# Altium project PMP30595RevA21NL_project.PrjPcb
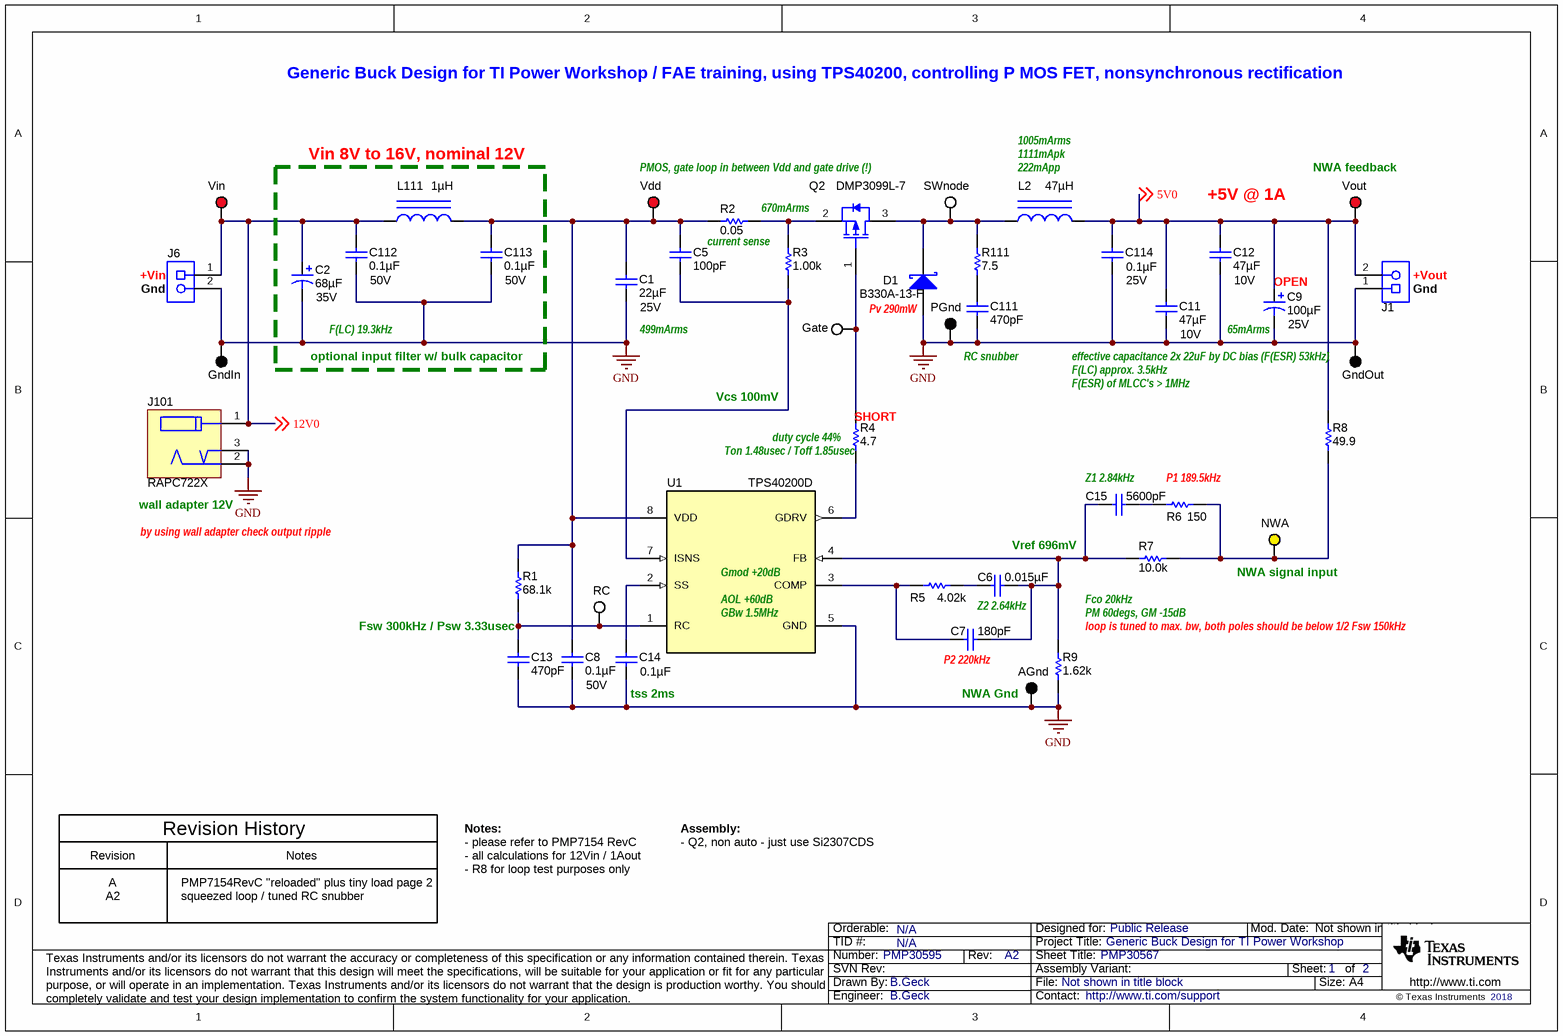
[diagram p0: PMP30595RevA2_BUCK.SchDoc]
CopyrightYear: 2018; EVM_Orderable: N/A; PCB_Rev: A21NL; PRJ_Customer: Public Release; PRJ_Engineer: B.Geck; PRJ_Number: PMP30595; PRJ_Title: Generic Buck Design for TI Power Workshop; SCH_Rev: A2; TechSupport: http://www.ti.com/support; TID: N/A
2 sheets, 77 parts. Net scope: global (net labels, ports and power ports of the same name join across sheets).
Board file: PMP30595RevA21NL_board.PcbDoc
Sheets:
  PMP30595RevA2_BUCK.SchDoc
  PMP30595RevA2_LOAD.SchDoc

## Sheet PMP30595RevA2_BUCK.SchDoc: PMP30567
size A4; Date: Not shown in title block; ApprovedBy: Not shown in title block; CheckedBy: Not shown in title block; Author: Not shown in title block; CompanyName: Not shown in title block; DrawnBy: B.Geck; Organization: Not shown in title block; Address1: Not shown in title block; Address2: Not shown in title block; Address3: Not shown in title block; Address4: Not shown in title block; DocumentNumber: 1; Revision: Use project parameter SCH_Rev; SheetNumber: 1; SheetTotal: 2; PageSetup: Record=PageOptions¦CenterHorizontal=True¦CenterVertical=True¦PrintScale=0.62¦XCorrection=1.00¦YCorrection=1.00¦PrintKind=0¦BorderSize=5000000¦LeftOffset=0¦BottomOffset=0¦Orientation=2¦PaperLength=1000¦PaperWidth=1000¦Scale=100¦PaperSource=15¦PrintQuality=600¦MediaType=1¦DitherType=10¦PrintScaleMode=1¦PaperKind=Letter

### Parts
AGnd  5011  [Keystone5011]  (value not drawn)
C1  ValueDisplayed: 22µF  Value2: 25V  [1210_270]  (hidden comment: GRM32ER71E226KE15L)
C2  ValueDisplayed: 68µF  Value2: 35V  [SM_RADIAL_6.3BMM]  (hidden comment: EEHZC1V680XP)
C5  ValueDisplayed: 100pF  [0603]  (hidden comment: GRM1885C1H101JA01D)
C6  ValueDisplayed: 0.015µF  [0603]  (hidden comment: GRM188R71E153KA01D)
C7  ValueDisplayed: 180pF  [0603]  (hidden comment: GRM1885C1H181JA01D)
C8  ValueDisplayed: 0.1µF  Value2: 50V  [0603]  (hidden comment: GCM188R71H104KA57D)
C9  ValueDisplayed: 100µF  Value2: 25V  [SM_RADIAL_6.3BMM]  (hidden comment: EEHZC1E101XP)
C11  ValueDisplayed: 47µF  Value2: 10V  [1210_270]  (hidden comment: GRM32ER71A476KE15L)
C12  ValueDisplayed: 47µF  Value2: 10V  [1210_270]  (hidden comment: GRM32ER71A476KE15L)
C13  ValueDisplayed: 470pF  [0603]  (hidden comment: GRM188R71H471KA01D)
C14  ValueDisplayed: 0.1µF  [0603]  (hidden comment: GRM188R71E104KA01D)
C15  ValueDisplayed: 5600pF  [0603]  (hidden comment: GRM188R71E562KA01D)
C111  ValueDisplayed: 470pF  [0603]  (hidden comment: GRM188R71H471KA01D)
C112  ValueDisplayed: 0.1µF  Value2: 50V  [0603]  (hidden comment: GCM188R71H104KA57D)
C113  ValueDisplayed: 0.1µF  Value2: 50V  [0603]  (hidden comment: GCM188R71H104KA57D)
C114  ValueDisplayed: 0.1µF  Value2: 25V  [0603]  (hidden comment: GRM188R71E104KA01D)
D1  B330A-13-F  [SMA]
Gate  5012  [Keystone5012]  (value not drawn)
GndIn  5011  [Keystone5011]  (value not drawn)
GndOut  5011  [Keystone5011]  (value not drawn)
J1  691 101 710 002  [Wurth_691101710002]  (value not drawn)
J6  691 101 710 002  [Wurth_691101710002]  (value not drawn)
J101  RAPC722X  [CONN_RAPC722X]
L2  ValueDisplayed: 47µH  [MSS1048]  (hidden comment: MSS1048-473MLB)
L111  ValueDisplayed: 1µH  [XFL4020]  (hidden comment: XFL4020-102MEB)
NWA  5014  [Keystone5014]  (value not drawn)
PGnd  5011  [Keystone5011]  (value not drawn)
Q2  DMP3099L-7  [SOT-23]
R1  ValueDisplayed: 68.1k  [0603]  (hidden comment: CRCW060368K1FKEA)
R2  ValueDisplayed: 0.05  [0805_HV]  (hidden comment: CRM0805-FW-R050ELF)
R3  ValueDisplayed: 1.00k  [0603]  (hidden comment: CRCW06031K00FKEA)
R4  ValueDisplayed: 4.7  [0603]  (hidden comment: CRCW06034R70JNEA)
R5  ValueDisplayed: 4.02k  [0603]  (hidden comment: CRCW06034K02FKEA)
R6  ValueDisplayed: 150  [0603]  (hidden comment: CRCW0603150RFKEA)
R7  ValueDisplayed: 10.0k  [0603]  (hidden comment: CRCW060310K0FKEA)
R8  ValueDisplayed: 49.9  [0603]  (hidden comment: CRCW060349R9FKEA)
R9  ValueDisplayed: 1.62k  [0603]  (hidden comment: CRCW06031K62FKEA)
R111  ValueDisplayed: 7.5  [0805_HV]  (hidden comment: CRCW08057R50JNEA)
RC  5012  [Keystone5012]  (value not drawn)
SWnode  5012  [Keystone5012]  (value not drawn)
U1  TPS40200D  [D0008A_N]
Vdd  5010  [Keystone5010]  (value not drawn)
Vin  5010  [Keystone5010]  (value not drawn)
Vout  5010  [Keystone5010]  (value not drawn)

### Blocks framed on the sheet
Vin 8V to 16V, nominal 12V: C2 C112 C113 L111

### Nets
GND: AGnd.1 C1.2 C2.2(-) C8.2 C9.2(-) C11.2 C12.2 C13.2 C14.2 C111.2 C112.2 C113.2 C114.2 D1.2(A) GndIn.1 GndOut.1 J1.1 J6.2 J101.2 J101.3 PGnd.1 R9.1 U1.5(GND)
5V0: C9.1(+) C11.1 C12.1 C114.1 J1.2 L2.2 R8.1 Vout.1 ; off-sheet 5V0
12V0: C2.1(+) C112.1 J6.1 J101.1 L111.1 Vin.1 ; off-sheet 12V0
NetC1_1: C1.1 C5.1 C8.1 C113.1 L111.2 R1.2 R2.1 U1.8(VDD) Vdd.1
NetC5_2: C5.2 R3.1 U1.7(ISNS)
NetC6_1: C6.1 C7.1 C15.2 R7.2 R9.2 U1.4(FB)
NetC6_2: C6.2 R5.2
NetC7_2: C7.2 R5.1 U1.3(COMP)
NetC13_1: C13.1 R1.1 RC.1 U1.1(RC)
NetC14_1: C14.1 U1.2(SS)
NetC15_1: C15.1 R6.1
NetC111_1: C111.1 R111.1
NetD1_1: D1.1(K) L2.1 Q2.3(D) R111.2 SWnode.1
NetGate_1: Gate.1 Q2.1(G) R4.2
NetNWA_1: NWA.1 R6.2 R7.1 R8.2
NetQ2_2: Q2.2(S) R2.2 R3.2
NetR4_1: R4.1 U1.6(GDRV)

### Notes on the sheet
- Generic Buck Design for TI Power Workshop / FAE training, using TPS40200, controlling P MOS FET, nonsynchronous rectification
- PMOS, gate loop in between Vdd and gate drive (!)
- 1111mApk
- 1005mArms
- (near L2) 222mApp
- (near Vout) NWA feedback
- (near R3) current sense
- (near R2) 670mArms
- (near C12) +5V @ 1A
- (near J6) +Vin
- (near J6) Gnd
- (near D1) Pv 290mW
- (near C9) OPEN
- (near J1) +Vout
- (near J1) Gnd
- F(LC) 19.3kHz
- optional input filter w/ bulk capacitor
- (near C1) 499mArms
- RC snubber
- (near C11) F(LC) approx. 3.5kHz
- F(ESR) of MLCC's > 1MHz
- effective capacitance 2x 22uF by DC bias
- (near C9) 65mArms
- (near GndOut) (F(ESR) 53kHz)
- Vcs 100mV
- (near R4) duty cycle 44%
- (near R4) Ton 1.48usec / Toff 1.85usec
- (near R4) SHORT
- (near J101) wall adapter 12V
- Z1 2.84kHz
- (near R6) P1 189.5kHz
- by using wall adapter check output ripple
- (near U1) Gmod +20dB
- Vref 696mV
- (near NWA) NWA signal input
- Fsw 300kHz / Psw 3.33usec
- (near U1) GBw 1.5MHz
- (near U1) AOL +60dB
- (near C7) P2 220kHz
- (near C6) Z2 2.64kHz
- Fco 20kHz
- PM 60degs, GM -15dB
- (near R9) loop is tuned to max. bw, both poles should be below 1/2 Fsw 150kHz
- (near C14) tss 2ms
- (near AGnd) NWA Gnd
- Revision
- Revision History
- Notes
- Notes:
- - please refer to PMP7154 RevC
- - all calculations for 12Vin / 1Aout
- Assembly:
- - Q2, non auto - just use Si2307CDS
- A
- A2
- PMP7154RevC "reloaded" plus tiny load page 2
- squeezed loop / tuned RC snubber
- - R8 for loop test purposes only

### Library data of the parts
AGnd GndIn GndOut PGnd = 5011: Test Point, Multipurpose, Black, TH; Manufacturer: Keystone; CompType: Test Point Loop; ContactFinish: Silver
C1 = GRM32ER71E226KE15L: CAP, CERM, 22 µF, 25 V,+/- 10%, X7R, 1210; Manufacturer: MuRata; Polarized: N; CompType: Capacitor; Value: 22uF; U/M: EA; Cap_F: 0.000022; Tolerance_%: 10; ESR_ohm: 0.002334; Value1: 0.002334 ohm; VDC_V: 25; IRMS_A: 3.832999; TaMin_C: -55; TaMax_C: 125; Cap_Case: 1210; SizeArea_mm2: 8; SizeAreaWB_mm2: 14.7; SizeX_mm: 3.2; SizeY_mm: 2.5; SizeZ_mm: 2.7; AEC Category: Q200; Green_Lifecycle: Active; Green_REACh: Passed
C2 = EEHZC1V680XP: CAP, Polymer Hybrid, 68 µF, 35 V,+/- 20%, 35 ohm, 6.3x7.7 SMD; Manufacturer: Panasonic; Polarized: Y; CompType: Capacitor; Value: 68uF; U/M: EA; Cap_F: 0.000068; Tolerance_%: 20; Value1: 35 ohm; VDC_V: 35; IRMS_A: 1.4; TaMin_C: -55; TaMax_C: 125; SizeAreaWB_mm2: 79.98; SizeArea_mm2: 48.18; SizeX_mm: 7.3; SizeY_mm: 6.6; SizeZ_mm: 7.7; AEC Category: Q200
C5 = GRM1885C1H101JA01D: CAP, CERM, 100 pF, 50 V,+/- 5%, C0G/NP0, 0603; Manufacturer: MuRata; Polarized: N; CompType: Capacitor; Value: 100pF; U/M: EA; Cap_F: 0.0000000001; Tolerance_%: 5; VDC_V: 50; Value2: 50V; TaMin_C: -55; TaMax_C: 125; SizeArea_mm2: 1.28; SizeAreaWB_mm2: 4.68; SizeX_mm: 1.6; SizeY_mm: 0.8; SizeZ_mm: 1; AEC Category: Q200; Green_Lifecycle: Active; Green_REACh: Passed
C6 = GRM188R71E153KA01D: CAP, CERM, 0.015 µF, 25 V,+/- 10%, X7R, 0603; Manufacturer: MuRata; Polarized: N; CompType: Capacitor; Value: 0.015uF; U/M: EA; Cap_F: 0.000000015; Tolerance_%: 10; VDC_V: 25; Value2: 25V; TaMin_C: -55; TaMax_C: 125; SizeArea_mm2: 1.28; SizeAreaWB_mm2: 4.68; SizeX_mm: 1.6; SizeY_mm: 0.8; SizeZ_mm: 1; AEC Category: Q200; Green_Lifecycle: Active; Green_REACh: Passed
C7 = GRM1885C1H181JA01D: CAP, CERM, 180 pF, 50 V,+/- 5%, C0G/NP0, 0603; Manufacturer: MuRata; Polarized: N; CompType: Capacitor; Value: 180pF; U/M: EA; Cap_F: 0.00000000018; Tolerance_%: 5; VDC_V: 50; Value2: 50V; TaMin_C: -55; TaMax_C: 125; SizeArea_mm2: 1.28; SizeAreaWB_mm2: 4.68; SizeX_mm: 1.6; SizeY_mm: 0.8; SizeZ_mm: 1; AEC Category: Q200; Green_Lifecycle: Active; Green_REACh: Passed
C8 C112 C113 = GCM188R71H104KA57D: CAP, CERM, 0.1 µF, 50 V,+/- 10%, X7R, 0603; Manufacturer: MuRata; Polarized: N; CompType: Capacitor; Value: 0.1uF; U/M: EA; Cap_F: 0.0000001; Tolerance_%: 10; ESR_ohm: 0.02; Value1: 0.02 ohm; VDC_V: 50; IRMS_A: 1.84; TaMin_C: -55; TaMax_C: 125; SizeArea_mm2: 1.28; SizeAreaWB_mm2: 4.68; SizeX_mm: 1.6; SizeY_mm: 0.8; SizeZ_mm: 1; AEC Category: Q200; Green_Lifecycle: Active; Green_REACh: Passed
C9 = EEHZC1E101XP: CAP, Polymer Hybrid, 100 µF, 25 V,+/- 20%, 30 ohm, 6.3x7.7 SMD; Manufacturer: Panasonic; Polarized: Y; CompType: Capacitor; Value: 100uF; U/M: EA; Cap_F: 0.0001; Tolerance_%: 20; Value1: 30 ohm; VDC_V: 25; ESR_ohm: 30; IRMS_A: 1.4; TaMin_C: -55; TaMax_C: 125; SizeAreaWB_mm2: 79.98; SizeArea_mm2: 48.18; SizeX_mm: 7.3; SizeY_mm: 6.6; SizeZ_mm: 7.7; AEC Category: Q200
C11 C12 = GRM32ER71A476KE15L: CAP, CERM, 47 µF, 10 V,+/- 10%, X7R, 1210; Manufacturer: MuRata; Polarized: N; CompType: Capacitor; Value: 47uF; U/M: EA; Cap_F: 0.000047; Tolerance_%: 10; TaMin_C: -55; TaMax_C: 125; Cap_Case: 1210; SizeArea_mm2: 8; SizeAreaWB_mm2: 14.7; SizeX_mm: 3.2; SizeY_mm: 2.5; SizeZ_mm: 2.7; AEC Category: Q200; Green_Lifecycle: Active; Green_REACh: Passed
C13 C111 = GRM188R71H471KA01D: CAP, CERM, 470 pF, 50 V,+/- 10%, X7R, 0603; Manufacturer: MuRata; Polarized: N; CompType: Capacitor; Value: 470pF; U/M: EA; Cap_F: 0.00000000047; Tolerance_%: 10; VDC_V: 50; Value2: 50V; TaMin_C: -55; TaMax_C: 125; SizeArea_mm2: 1.28; SizeAreaWB_mm2: 4.68; SizeX_mm: 1.6; SizeY_mm: 0.8; SizeZ_mm: 1; AEC Category: Q200; Green_Lifecycle: Active; Green_REACh: Passed
C14 = GRM188R71E104KA01D: CAP, CERM, 0.1 µF, 25 V, +/- 10%, X7R, 0603; Manufacturer: MuRata; Polarized: N; CompType: Capacitor; Value: 0.1uF; U/M: EA; Cap_F: 0.0000001; Tolerance_%: 10; Value1: Unknown; VDC_V: 25; Value2: 25V; TaMin_C: -55; TaMax_C: 125; SizeArea_mm2: 1.28; SizeAreaWB_mm2: 4.68; SizeX_mm: 1.6; SizeY_mm: 0.8; SizeZ_mm: 1; AEC Category: Q200
C15 = GRM188R71E562KA01D: CAP, CERM, 5600 pF, 25 V,+/- 10%, X7R, 0603; Manufacturer: MuRata; Polarized: N; CompType: Capacitor; Value: 5600pF; U/M: EA; Cap_F: 0.0000000056; Tolerance_%: 10; VDC_V: 25; Value2: 25V; TaMin_C: -55; TaMax_C: 125; SizeArea_mm2: 1.28; SizeAreaWB_mm2: 4.68; SizeX_mm: 1.6; SizeY_mm: 0.8; SizeZ_mm: 1; AEC Category: Q200
C114 = GRM188R71E104KA01D: CAP, CERM, 0.1 µF, 25 V, +/- 10%, X7R, 0603; Manufacturer: MuRata; Polarized: N; CompType: Capacitor; Value: 0.1uF; U/M: EA; Cap_F: 0.0000001; Tolerance_%: 10; Value1: Unknown; VDC_V: 25; TaMin_C: -55; TaMax_C: 125; SizeArea_mm2: 1.28; SizeAreaWB_mm2: 4.68; SizeX_mm: 1.6; SizeY_mm: 0.8; SizeZ_mm: 1; AEC Category: Q200
D1 = B330A-13-F: Diode, Schottky, 30 V, 3 A, SMA; Manufacturer: Diodes Inc.; U/M: EA; Vf_V: 0.5; Value: 30V; Value1: 3A; Value2: 0.5V; Io_A: 3; Vr_V: 30; TJmax_C: 125; RJC_CperW: 25; SizeAreaWB_mm2: 37.3428; SizeArea_mm2: 16.3228; SizeX_mm: 5.59; SizeY_mm: 2.92; SizeZ_mm: 2.87; AEC Category: Q101; Green_Lifecycle: Active; Green_REACh: Passed
Gate RC SWnode = 5012: Test Point, Multipurpose, White, TH; Manufacturer: Keystone; CompType: Test Point Loop; ContactFinish: Silver; Green_Lifecycle: Active; Green_REACh: Passed
J1 J6 = 691 101 710 002: Terminal Block, 5 mm, 2x1, Tin, TH; Manufacturer: Wurth Elektronik; SymbolCreator: a0412235
J101 = RAPC722X: Power Jack, mini, 2.1mm OD, R/A, TH; Manufacturer: Switchcraft; SymbolCreator: a0799628; Green_Lifecycle: Not Set; Green_REACh: Incomplete
L2 = MSS1048-473MLB: Inductor, Shielded Drum Core, Ferrite, 47 µH, 2.2 A, 0.13 ohm, SMD; Manufacturer: Coilcraft; Value: 47uH; Ind_H: 47.0E-6; Imax_A: 2.2; Irms: 2.42A @ 40C rise; Isat: 2.2A @ 30% inductance drop; DCR_ohm: 0.13; Value2: 2.2A; SizeAreaWB_mm2: 146.4; SizeArea_mm2: 102; SizeX_mm: 10.2; SizeY_mm: 10; SizeZ_mm: 4.8; AEC Category: Q200; Green_Lifecycle: Not Set; Green_REACh: Incomplete
L111 = XFL4020-102MEB: Inductor, Shielded, Composite, 1 µH, 5.4 A, 0.01 ohm, SMD; Manufacturer: Coilcraft; Value: 1uH; Ind_H: 1.0E-6; Imax_A: 5.4; Irms: 11A @ 40C rise; Isat: 5.4A @ 30% inductance drop; DCR_ohm: 0.01; Value2: 5.4A; SizeAreaWB_mm2: 25; SizeArea_mm2: 16; SizeX_mm: 4; SizeZ_mm: 2.15; AEC Category: Q200; Green_Lifecycle: Not Set; Green_REACh: Incomplete
NWA = 5014: Test Point, Multipurpose, Yellow, TH; Manufacturer: Keystone; CompType: Test Point Loop; ContactFinish: Silver; Green_Lifecycle: Active; Green_REACh: Passed
Q2 = DMP3099L-7: MOSFET, P-CH, -30 V, -3.8 A, AEC-Q101, SOT-23; Manufacturer: Diodes Inc.; Alternate Manufacturer: None; U/M: EA; ChType: P; Value: -30V; Value1: ? ohm; Value2: 5.2 nC; QgTyp_nC: 5.2; Vgs_V: -20; SizeAreaWB_mm2: 14; SizeArea_mm2: 7.5; SizeX_mm: 2.5; SizeY_mm: 3; SizeZ_mm: 1.1; AEC Category: Q101; AEC Qualified: Y; Green_Lifecycle: Active; Green_REACh: Passed
R1 = CRCW060368K1FKEA: RES, 68.1 k, 1%, 0.1 W, 0603; Manufacturer: Vishay-Dale; CompType: Resistor; Value: 68.1k; Res_ohm: 68100; Value_Code: 68k1; Tolerance_%: 1; Power_W: 0.1; Value2: 0.1W; VDC_V: 75; TempCo: 100 ppm/C; SizeArea_mm2: 1.28; SizeX_mm: 1.6; SizeY_mm: 0.8; EIA_Code: E96; U/M: EA; AEC Category: Q200; Green_Lifecycle: Active; Green_REACh: Passed
R2 = CRM0805-FW-R050ELF: RES, 0.05, 1%, 0.25 W, 0805; Manufacturer: Bourns; CompType: Resistor; Value: 0.05; Value_Code: R050; Tolerance_%: 1; Power_W: 0.25; Value2: 0.25W; VDC_V: 0; TempCo: 150 ppm/C; SizeArea_mm2: 2.5; SizeX_mm: 2; SizeY_mm: 1.25; SizeZ_mm: 1.45; EIA_Code: E96; U/M: EA; AEC Category: Q200
R3 = CRCW06031K00FKEA: RES, 1.00 k, 1%, 0.1 W, 0603; Manufacturer: Vishay-Dale; CompType: Resistor; Value: 1.00k; Res_ohm: 1000; Value_Code: 1k00; Tolerance_%: 1; Power_W: 0.1; Value2: 0.1W; VDC_V: 75; TempCo: 100 ppm/C; SizeArea_mm2: 1.28; SizeX_mm: 1.6; SizeY_mm: 0.8; EIA_Code: E96; U/M: EA; AEC Category: Q200; Green_Lifecycle: Active; Green_REACh: Passed
R4 = CRCW06034R70JNEA: RES, 4.7, 5%, 0.1 W, 0603; Manufacturer: Vishay-Dale; CompType: Resistor; Value: 4.7; Value_Code: 4R70; Tolerance_%: 5; Power_W: 0.1; Value2: 0.1W; VDC_V: 75; TempCo: 200 ppm/C; SizeArea_mm2: 1.28; SizeX_mm: 1.6; SizeY_mm: 0.8; SizeZ_mm: 1; EIA_Code: E24; U/M: EA; AEC Category: Q200; Green_Lifecycle: Active; Green_REACh: Passed
R5 = CRCW06034K02FKEA: RES, 4.02 k, 1%, 0.1 W, 0603; Manufacturer: Vishay-Dale; CompType: Resistor; Value: 4.02k; Res_ohm: 4020; Value_Code: 4k02; Tolerance_%: 1; Power_W: 0.1; Value2: 0.1W; VDC_V: 75; TempCo: 100 ppm/C; SizeArea_mm2: 1.28; SizeX_mm: 1.6; SizeY_mm: 0.8; EIA_Code: E96; U/M: EA; AEC Category: Q200; Green_Lifecycle: Active; Green_REACh: Passed
R6 = CRCW0603150RFKEA: RES, 150, 1%, 0.1 W, 0603; Manufacturer: Vishay-Dale; CompType: Resistor; Value: 150; Value_Code: 150R; Tolerance_%: 1; Power_W: 0.1; Value2: 0.1W; VDC_V: 75; TempCo: 100 ppm/C; SizeArea_mm2: 1.28; SizeX_mm: 1.6; SizeY_mm: 0.8; EIA_Code: E96; U/M: EA; AEC Category: Q200; Green_Lifecycle: Active; Green_REACh: Passed
R7 = CRCW060310K0FKEA: RES, 10.0 k, 1%, 0.1 W, 0603; Manufacturer: Vishay-Dale; CompType: Resistor; Value: 10.0k; Res_ohm: 10000; Value_Code: 10k0; Tolerance_%: 1; Power_W: 0.1; Value2: 0.1W; VDC_V: 75; TempCo: 100 ppm/C; SizeArea_mm2: 1.28; SizeX_mm: 1.6; SizeY_mm: 0.8; EIA_Code: E96; U/M: EA; AEC Category: Q200; Green_Lifecycle: Active; Green_REACh: Passed
R8 = CRCW060349R9FKEA: RES, 49.9, 1%, 0.1 W, 0603; Manufacturer: Vishay-Dale; CompType: Resistor; Value: 49.9; Value_Code: 49R9; Tolerance_%: 1; Power_W: 0.1; Value2: 0.1W; VDC_V: 75; TempCo: 100 ppm/C; SizeArea_mm2: 1.28; SizeX_mm: 1.6; SizeY_mm: 0.8; EIA_Code: E96; U/M: EA; AEC Category: Q200; Green_Lifecycle: Active; Green_REACh: Passed
R9 = CRCW06031K62FKEA: RES, 1.62 k, 1%, 0.1 W, 0603; Manufacturer: Vishay-Dale; CompType: Resistor; Value: 1.62k; Res_ohm: 1620; Value_Code: 1k62; Tolerance_%: 1; Power_W: 0.1; Value2: 0.1W; VDC_V: 75; TempCo: 100 ppm/C; SizeArea_mm2: 1.28; SizeX_mm: 1.6; SizeY_mm: 0.8; EIA_Code: E96; U/M: EA; AEC Category: Q200; Green_Lifecycle: Active; Green_REACh: Passed
R111 = CRCW08057R50JNEA: RES, 7.5, 5%, 0.125 W, 0805; Manufacturer: Vishay-Dale; CompType: Resistor; Value: 7.5; Value_Code: 7R50; Tolerance_%: 5; Power_W: 0.125; Value2: 0.125W; VDC_V: 150; TempCo: 200 ppm/C; SizeArea_mm2: 2.5; SizeX_mm: 2; SizeY_mm: 1.25; SizeZ_mm: 1.45; EIA_Code: E24; U/M: EA; AEC Category: Q200
U1 = TPS40200D: Wide Input Non-Synchronous Buck DC/DC Controller, D0008A (SOIC-8); Manufacturer: Texas Instruments; SymbolCreator: Altium; SizeArea_mm2: 30.38; SizeAreaWB_mm2: 56.58; SizeX_mm: 4.9; SizeY_mm: 6.2; SizeZ_mm: 1.75; CompType: IC; U/M: EA; Green_Lifecycle: Active; Green_REACh: Passed
Vdd Vin Vout = 5010: Test Point, Multipurpose, Red, TH; Manufacturer: Keystone; CompType: Test Point Loop; ContactFinish: Silver

## Sheet PMP30595RevA2_LOAD.SchDoc
size A4; Date: Not shown in title block; ApprovedBy: Not shown in title block; CheckedBy: Not shown in title block; Author: Not shown in title block; CompanyName: Not shown in title block; Engineer: Not shown in title block; Organization: Not shown in title block; Address1: Not shown in title block; Address2: Not shown in title block; Address3: Not shown in title block; Address4: Not shown in title block; DocumentNumber: 2; Revision: Use project parameter SCH_Rev; SheetNumber: 2; SheetTotal: 2; PageSetup: Record=PageOptions¦CenterHorizontal=True¦CenterVertical=True¦PrintScale=1.00¦XCorrection=1.00¦YCorrection=1.00¦PrintKind=0¦BorderSize=5000000¦LeftOffset=0¦BottomOffset=0¦Orientation=2¦PaperLength=1000¦PaperWidth=1000¦Scale=100¦PaperSource=15¦PrintQuality=600¦MediaType=1¦DitherType=10¦PaperKind=Letter¦PrintScaleMode=1
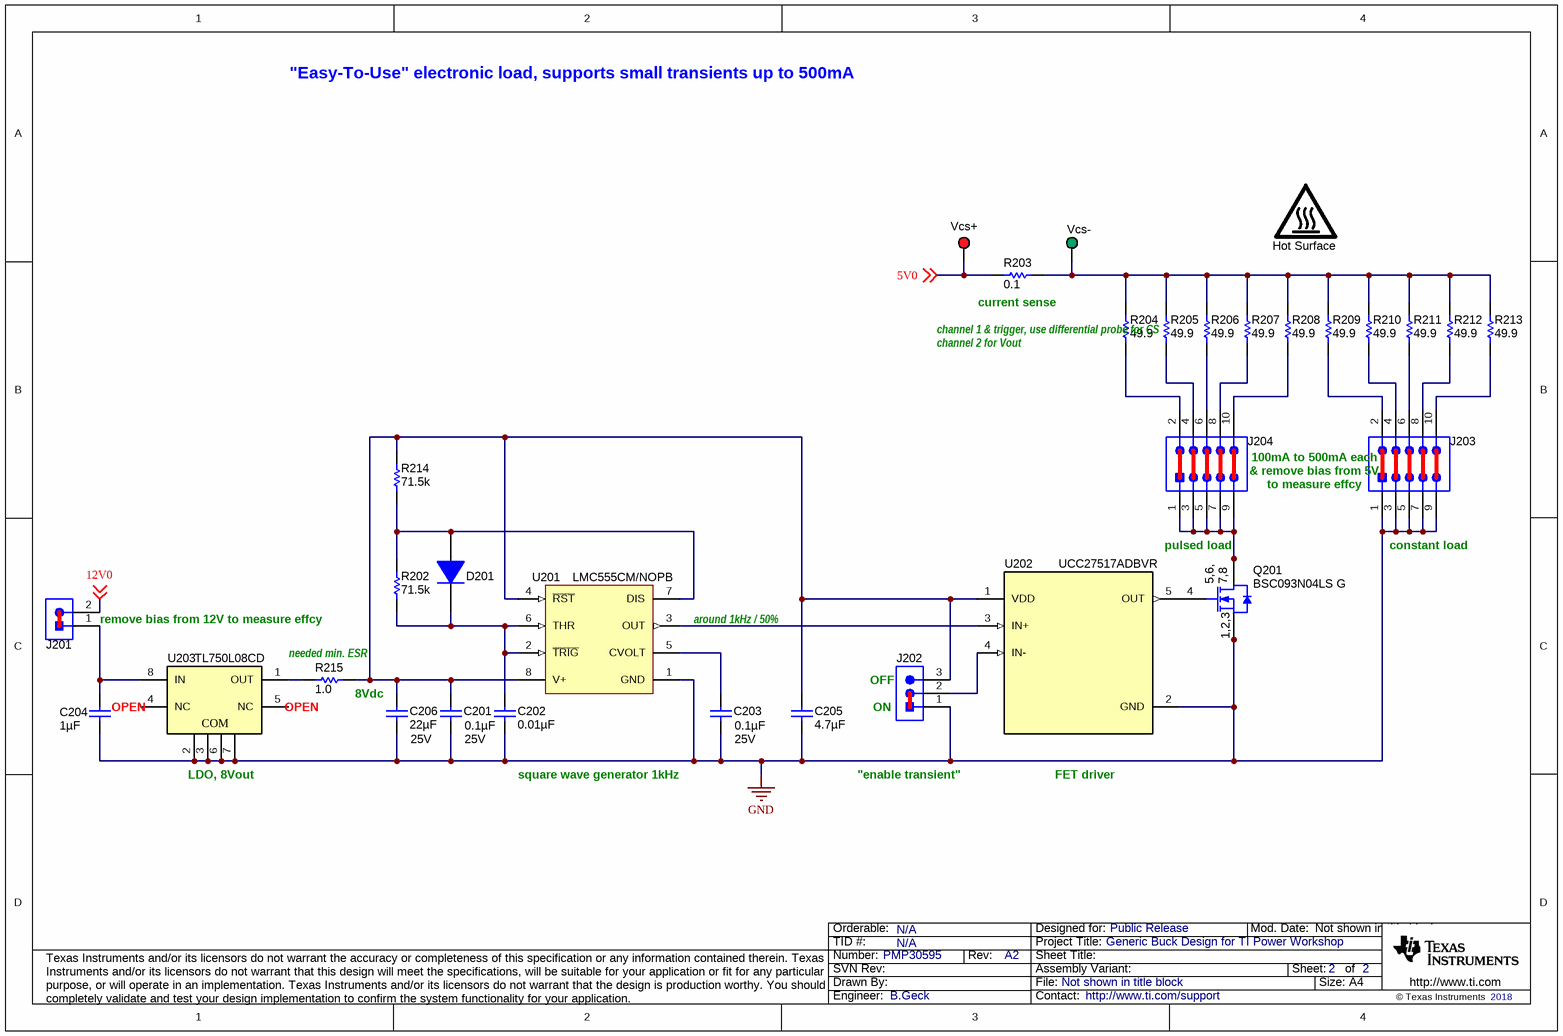
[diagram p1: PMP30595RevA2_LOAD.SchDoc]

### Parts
C201  ValueDisplayed: 0.1µF  Value2: 25V  [0603]  (hidden comment: GRM188R71E104KA01D)
C202  ValueDisplayed: 0.01µF  [0603]  (hidden comment: GRM188R71E103KA01D)
C203  ValueDisplayed: 0.1µF  Value2: 25V  [0603]  (hidden comment: GRM188R71E104KA01D)
C204  ValueDisplayed: 1µF  [0603]  (hidden comment: GRM188R71E105KA12D)
C205  ValueDisplayed: 4.7µF  [0805_HV]  (hidden comment: GRM21BR71E475KA73L)
C206  ValueDisplayed: 22µF  Value2: 25V  [1210_270]  (hidden comment: GRM32ER71E226KE15L)
D201  1N4148WFL-G3-08  [SOD-123FL]  (value not drawn)
Hot_Surface  CAUTION HOT SURFACE  [IEC_HotSurface_Medium]  (value not drawn)  (no BOM)
J201  TSW-102-07-G-S  [TSW-102-07-G-S]  (value not drawn)
J202  TSW-103-07-G-S  [TSW-103-07-G-S]  (value not drawn)
J203  TSW-105-07-G-D  [TSW-105-07-G-D]  (value not drawn)
J204  TSW-105-07-G-D  [TSW-105-07-G-D]  (value not drawn)
Q201  BSC093N04LS G  [PG-TDSON-8]
R202  ValueDisplayed: 71.5k  [0603]  (hidden comment: CRCW060371K5FKEA)
R203  ValueDisplayed: 0.1  [1206]  (hidden comment: CSR1206FKR100)
R204  ValueDisplayed: 49.9  [2010]  (hidden comment: CRCW201049R9FKEF)
R205  ValueDisplayed: 49.9  [2010]  (hidden comment: CRCW201049R9FKEF)
R206  ValueDisplayed: 49.9  [2010]  (hidden comment: CRCW201049R9FKEF)
R207  ValueDisplayed: 49.9  [2010]  (hidden comment: CRCW201049R9FKEF)
R208  ValueDisplayed: 49.9  [2010]  (hidden comment: CRCW201049R9FKEF)
R209  ValueDisplayed: 49.9  [2010]  (hidden comment: CRCW201049R9FKEF)
R210  ValueDisplayed: 49.9  [2010]  (hidden comment: CRCW201049R9FKEF)
R211  ValueDisplayed: 49.9  [2010]  (hidden comment: CRCW201049R9FKEF)
R212  ValueDisplayed: 49.9  [2010]  (hidden comment: CRCW201049R9FKEF)
R213  ValueDisplayed: 49.9  [2010]  (hidden comment: CRCW201049R9FKEF)
R214  ValueDisplayed: 71.5k  [0603]  (hidden comment: CRCW060371K5FKEA)
R215  ValueDisplayed: 1.0  [0603]  (hidden comment: CRCW06031R00JNEA)
U201  LMC555CM/NOPB  [M08A_N]
U202  UCC27517ADBVR  [DBV0005A_N]
U203  TL750L08CD  [D0008A_N]
Vcs+  5010  [Keystone5010]  (value not drawn)
Vcs-  5126  [Keystone5126]  (value not drawn)

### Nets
GND: C201.2 C202.2 C203.2 C204.2 C205.2 C206.2 J202.1 J203.1 J203.3 J203.5 J203.7 J203.9 Q201.1(S) Q201.2(S) Q201.3(S) U201.1(GND) U202.2(GND) U203.2(COM) U203.3(COM) U203.6(COM) U203.7(COM)
5V0: R203.1 Vcs+.1 ; off-sheet 5V0
12V0: J201.2 ; off-sheet 12V0
NetC201_1: C201.1 C205.1 C206.1 J202.3 R214.2 R215.2 U201.4(~{RST}) U201.8(V+) U202.1(VDD)
NetC202_1: C202.1 D201.1(K) R202.1 U201.2(~{TRIG}) U201.6(THR)
NetC203_1: C203.1 U201.5(CVOLT)
NetC204_1: C204.1 J201.1 U203.8(IN)
NetD201_2: D201.2(A) R202.2 R214.1 U201.7(DIS)
NetJ202_2: J202.2 U202.4(IN-)
NetJ203_2: J203.2 R209.1
NetJ203_4: J203.4 R210.1
NetJ203_6: J203.6 R211.1
NetJ203_8: J203.8 R212.1
NetJ203_10: J203.10 R213.1
NetJ204_1: J204.1 J204.3 J204.5 J204.7 J204.9 Q201.5(D) Q201.6(D) Q201.7(D) Q201.8(D) Q201.9(D)
NetJ204_2: J204.2 R204.1
NetJ204_4: J204.4 R205.1
NetJ204_6: J204.6 R206.1
NetJ204_8: J204.8 R207.1
NetJ204_10: J204.10 R208.1
NetQ201_4: Q201.4(G) U202.5(OUT)
NetR203_2: R203.2 R204.2 R205.2 R206.2 R207.2 R208.2 R209.2 R210.2 R211.2 R212.2 R213.2 Vcs-.1
NetR215_1: R215.1 U203.1(OUT)
NetU201_3: U201.3(OUT) U202.3(IN+)

Not connected (* = marked no-connect by the designer): U203 4(NC) 5(NC)

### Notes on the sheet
- "Easy-To-Use" electronic load, supports small transients up to 500mA
- (near R203) current sense
- channel 1 & trigger, use differential probe for CS
- channel 2 for Vout
- (near J203) 100mA to 500mA each
- (near J203) & remove bias from 5V
- to measure effcy
- pulsed load
- (near J203) constant load
- (near J201) remove bias from 12V to measure effcy
- needed min. ESR
- (near U201) around 1kHz / 50%
- OPEN
- 8Vdc
- (near J202) ON
- (near J202) OFF
- (near U203) LDO, 8Vout
- square wave generator 1kHz
- "enable transient"
- FET driver

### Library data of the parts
C201 C203 = GRM188R71E104KA01D: as C114 on sheet PMP30595RevA2_BUCK
C202 = GRM188R71E103KA01D: CAP, CERM, 0.01 µF, 25 V,+/- 10%, X7R, 0603; Manufacturer: MuRata; Polarized: N; CompType: Capacitor; Value: 0.01uF; U/M: EA; Cap_F: 0.00000001; Tolerance_%: 10; VDC_V: 25; Value2: 25V; TaMin_C: -55; TaMax_C: 125; SizeArea_mm2: 1.28; SizeAreaWB_mm2: 4.68; SizeX_mm: 1.6; SizeY_mm: 0.8; SizeZ_mm: 1; AEC Category: Q200; Green_Lifecycle: Active; Green_REACh: Passed
C204 = GRM188R71E105KA12D: CAP, CERM, 1 µF, 25 V,+/- 10%, X7R, 0603; Manufacturer: MuRata; Polarized: N; CompType: Capacitor; Value: 1uF; U/M: EA; Cap_F: 0.000001; Tolerance_%: 10; VDC_V: 25; Value2: 25V; TaMin_C: -55; TaMax_C: 125; SizeArea_mm2: 1.28; SizeAreaWB_mm2: 4.68; SizeX_mm: 1.6; SizeY_mm: 0.8; SizeZ_mm: 1; AEC Category: Q200; Green_Lifecycle: Active; Green_REACh: Passed
C205 = GRM21BR71E475KA73L: CAP, CERM, 4.7 µF, 25 V,+/- 10%, X7R, 0805; Manufacturer: MuRata; Polarized: N; CompType: Capacitor; Value: 4.7uF; U/M: EA; Cap_F: 0.0000047; Tolerance_%: 10; VDC_V: 25; Value2: 25V; TaMin_C: -55; TaMax_C: 125; Cap_Case: 0805; SizeArea_mm2: 2.5; SizeAreaWB_mm2: 6.75; SizeX_mm: 2; SizeY_mm: 1.25; SizeZ_mm: 1.45; AEC Category: Q200
C206 = GRM32ER71E226KE15L: as C1 on sheet PMP30595RevA2_BUCK
D201 = 1N4148WFL-G3-08: Diode, Switching, 100 V, 0.15 A, SOD-123FL; Manufacturer: Vishay-Semiconductor; U/M: EA; Vf_V: 1.2; Value: 100V; Value1: 0.15A; Value2: 1.2V; Io_A: 0.15; Vr_V: 100; TJmax_C: 150; SizeAreaWB_mm2: 12.19; SizeArea_mm2: 5.94; SizeX_mm: 3.6; SizeY_mm: 1.65; SizeZ_mm: 0.98; AEC Category: Q101; Green_Lifecycle: Not Set; Green_REACh: Incomplete
Hot_Surface = IEC_HotSurface: IEC 61010-1 Hot Surface Warning; SymbolCreator: a0412235
J201 = TSW-102-07-G-S: Header, 100mil, 2x1, Gold, TH; Manufacturer: Samtec; SymbolCreator: a0412235; Pitch_mm: 2.54; Gender: Male; Shrouded: N; Row_Count: 1; Current_A: 6.3; Voltage_V: 550; Cert_CSA: Y; Green_Lifecycle: Active; Green_REACh: Passed
J202 = TSW-103-07-G-S: Header, 100mil, 3x1, Gold, TH; Manufacturer: Samtec; SymbolCreator: a0799628; Pitch_mm: 2.54; Gender: Male; Shrouded: N; Row_Count: 1; Current_A: 6.3; Voltage_V: 550; Cert_CSA: Y; Green_Lifecycle: Active; Green_REACh: Passed
J203 J204 = TSW-105-07-G-D: Header, 100mil, 5x2, Gold, TH; Manufacturer: Samtec; SymbolCreator: a0412235; Pitch_mm: 2.54; Gender: Male; Shrouded: N; Row_Count: 2; Current_A: 6.3; Voltage_V: 550; Cert_CSA: Y; Green_Lifecycle: Active; Green_REACh: Passed
Q201 = BSC093N04LS G: MOSFET, N-CH, 40 V, 49 A, PG-TDSON-8; Manufacturer: Infineon Technologies; Alternate Manufacturer: None; U/M: EA; ChType: N; Value: 40V; VdsMax_V: 40; Value1: 0.0137 ohm; Rdson45_ohm: 0.0137; Value2: 18 nC; QgTyp_nC: 18; Vgs_V: 20; IdsMax_A: 49; SizeAreaWB_mm2: 55.131; SizeArea_mm2: 29.351; SizeX_mm: 5.99; SizeY_mm: 4.9; SizeZ_mm: 1.12; AEC Category: Q101; Green_Lifecycle: Not Set; Green_REACh: Incomplete
R202 R214 = CRCW060371K5FKEA: RES, 71.5 k, 1%, 0.1 W, 0603; Manufacturer: Vishay-Dale; CompType: Resistor; Value: 71.5k; Res_ohm: 71500; Value_Code: 71k5; Tolerance_%: 1; Power_W: 0.1; Value2: 0.1W; VDC_V: 75; TempCo: 100 ppm/C; SizeArea_mm2: 1.28; SizeX_mm: 1.6; SizeY_mm: 0.8; EIA_Code: E96; U/M: EA; AEC Category: Q200; Green_Lifecycle: Active; Green_REACh: Passed
R203 = CSR1206FKR100: RES, 0.1, 1%, 0.5 W, 1206; Manufacturer: Stackpole Electronics Inc; CompType: Resistor; Value: 0.1; Value_Code: R100; Tolerance_%: 1; Power_W: 0.5; Value2: 0.5W; TempCo: 100 ppm/C; SizeArea_mm2: 5.12; SizeX_mm: 3.2; SizeY_mm: 1.6; SizeZ_mm: 1.35; EIA_Code: E96; U/M: EA; AEC Category: Q200
R204-R213 = CRCW201049R9FKEF: RES, 49.9, 1%, 0.75 W, AEC-Q200 Grade 0, 2010; Manufacturer: Vishay-Dale; CompType: Resistor; Value: 49.9; Value_Code: 49R9; Tolerance_%: 1; Power_W: 0.75; Value2: 0.75W; VDC_V: 400; TempCo: 100 ppm/C; SizeArea_mm2: 12.5; SizeX_mm: 5; SizeY_mm: 2.5; SizeZ_mm: 1.66; EIA_Code: E96; U/M: EA; AEC Category: Q200; AEC Qualified: Y; AEC Grade: 0
R215 = CRCW06031R00JNEA: RES, 1.0, 5%, 0.1 W, 0603; Manufacturer: Vishay-Dale; CompType: Resistor; Value: 1.0; Res_ohm: 1; Value_Code: 1R00; Tolerance_%: 5; Power_W: 0.1; Value2: 0.1W; VDC_V: 75; TempCo: 200 ppm/C; SizeArea_mm2: 1.28; SizeX_mm: 1.6; SizeY_mm: 0.8; EIA_Code: E24; U/M: EA; AEC Category: Q200; Green_Lifecycle: Active; Green_REACh: Passed
U201 = LMC555CM/NOPB: CMOS Timer, 8-pin Narrow SOIC, Pb-Free; Manufacturer: Texas Instruments; PackageTopMarking: NSZXTT*LMC*555CM; PowerWise: N; CompType: Analog IC
U202 = UCC27517DBVR: 4A/4A Single Channel High-speed Low-side Gate Driver, DBV0005A (SOT-23-5); Alternate PartNumber: UCC27517DBVT; Manufacturer: Texas Instruments; SymbolCreator: Altium; SizeArea_mm2: 8.12; SizeAreaWB_mm2: 14.82; SizeX_mm: 2.8; SizeY_mm: 2.9; SizeZ_mm: 1.45; CompType: IC; U/M: EA; Green_Lifecycle: Active; Green_REACh: Passed
U203 = TL750L08CD: Single Output LDO, 150 mA, Fixed 8 V Output, 9 to 26 V Input, with Low IQ, 8-pin SOIC (D), 0 to 125 degC, Green (RoHS & no Sb/Br); Manufacturer: Texas Instruments; Alternate PartNumber: Equivalent; Accuracy(%): 4; Fixed Output Options(V): 8; Iout(Max)(A): 0.15; Iq(Typ)(mA): 1; Rating: Catalog; SubFamily: Single Channel LDO; Vdo(Typ)(mV): 600; Vin(Max)(V): 26; Vin(Min)(V): 9
Vcs+ = 5010: as Vdd on sheet PMP30595RevA2_BUCK
Vcs- = 5126: Test Point, Multipurpose, Green, TH; Manufacturer: Keystone; SymbolCreator: a0412235; CompType: Test Point Loop; ContactFinish: Silver; Green_Lifecycle: Active; Green_REACh: Passed

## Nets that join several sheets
GND: PMP30595RevA2_BUCK (23 pins), PMP30595RevA2_LOAD (21 pins)
5V0: PMP30595RevA2_BUCK (8 pins), PMP30595RevA2_LOAD (R203.1 Vcs+.1)
12V0: PMP30595RevA2_BUCK (6 pins), PMP30595RevA2_LOAD (J201.2)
